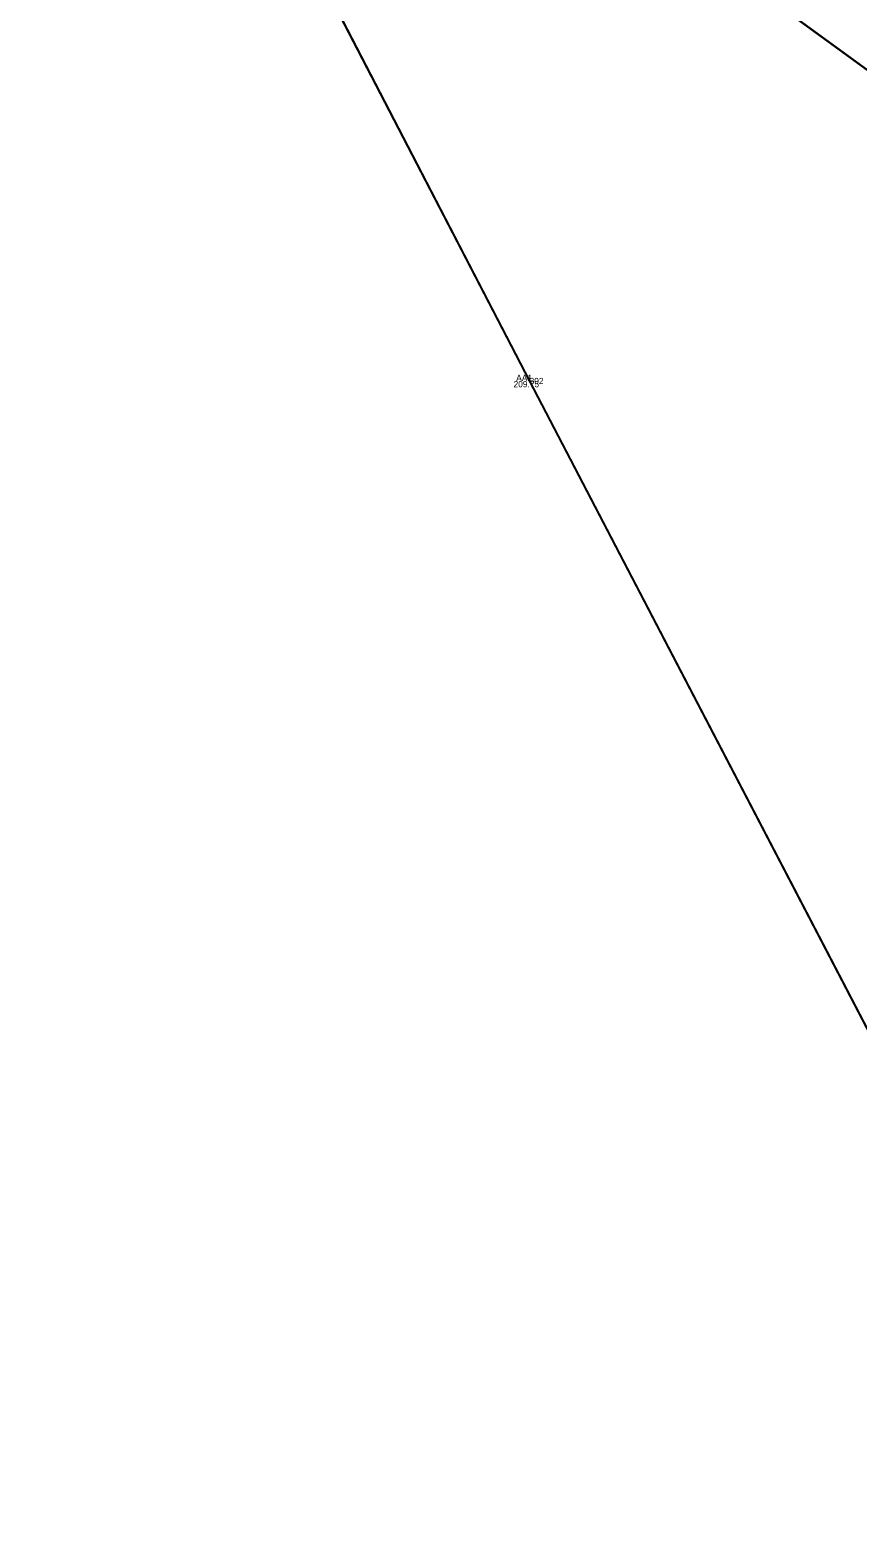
# Model space of a CAD drawing. Extents: x -263091 to -262565, y -1238731 to -1237092.
# Drawn here: x -262982.43 to -262955.92, y -1238442.76 to -1238394.45 of the extents above; entities that cross this region are included whole.
import ezdxf

# ---------------------------------------------------------------- set-up
doc = ezdxf.new("R2010")
doc.units = 0
for name, color, linetype in [('03_Asfalt', 7, 'Continuous'), ('10', 7, 'Continuous'), ('Groma (21)', 7, 'Continuous'), ('Groma (22)', 7, 'Continuous'), ('Groma (23)', 7, 'Continuous'), ('Groma (24)', 7, 'Continuous'), ('U001_Zeleň_mimo', 7, 'Continuous'), ('U002_Asfalt', 7, 'Continuous')]:
    doc.layers.add(name, color=color, linetype=linetype)

msp = doc.modelspace()

# ---------------------------------------------------------------- linework, layer by layer
at = {"layer": '03_Asfalt'}
for points in [[(-262974.83, -1238389.493), (-262966.434, -1238405.689), (-262952.335, -1238432.734), (-262942.188, -1238451.946), (-262934.983, -1238466.187), (-262921.957, -1238491.107), (-262911.861, -1238511.116), (-262905.822, -1238523.977), (-262900.647, -1238535.669), (-262888.764, -1238565.07), (-262881.2, -1238585.494), (-262874.644, -1238603.324)], [(-262804.465, -1238690.033), (-262818.631, -1238655.736), (-262826.695, -1238636.389), (-262836.855, -1238611.872), (-262842.406, -1238598.306), (-262850.452, -1238578.707), (-262858.82, -1238561.234), (-262870.509, -1238539), (-262873.344, -1238533.53), (-262876.375, -1238529.239), (-262880.031, -1238521.826), (-262869.115, -1238517.45), (-262870.175, -1238508.052), (-262871.319, -1238501.744), (-262886.895, -1238462.375), (-262895.067, -1238441.663), (-262905.824, -1238433.621), (-262917.716, -1238423.993), (-262928.896, -1238415.327), (-262941.774, -1238405.784), (-262954.673, -1238396.412), (-262962.054, -1238391.026)]]:
    msp.add_lwpolyline(points, dxfattribs=at)
at = {"layer": '10'}
msp.add_lwpolyline([(-262982.434, -1238375.977), (-262968.907, -1238386.238), (-262962.054, -1238391.026), (-262954.673, -1238396.412), (-262941.774, -1238405.784), (-262928.896, -1238415.327), (-262917.716, -1238423.993), (-262905.824, -1238433.621), (-262895.067, -1238441.663), (-262870.407, -1238460.6)], dxfattribs=at)
at = {"layer": 'Groma (21)'}
msp.add_circle((-262966.434, -1238405.689), 0.01, dxfattribs=at)
at = {"layer": 'U001_Zeleň_mimo'}
for points in [[(-262874.64, -1238603.32), (-262881.2, -1238585.49), (-262888.76, -1238565.07), (-262900.65, -1238535.67), (-262905.82, -1238523.98), (-262911.86, -1238511.12), (-262921.96, -1238491.11), (-262934.98, -1238466.19), (-262942.19, -1238451.95), (-262952.34, -1238432.73), (-262966.43, -1238405.69), (-262974.83, -1238389.49)], [(-262962.05, -1238391.03), (-262954.67, -1238396.41), (-262941.77, -1238405.78), (-262928.9, -1238415.33), (-262917.72, -1238423.99), (-262905.82, -1238433.62), (-262895.07, -1238441.66), (-262886.9, -1238462.38), (-262871.32, -1238501.74), (-262870.18, -1238508.05), (-262869.12, -1238517.45), (-262880.03, -1238521.83), (-262876.38, -1238529.24), (-262873.34, -1238533.53), (-262870.51, -1238539), (-262858.82, -1238561.23), (-262850.45, -1238578.71), (-262842.41, -1238598.31), (-262836.86, -1238611.87), (-262826.7, -1238636.39), (-262818.63, -1238655.74), (-262804.47, -1238690.03)]]:
    msp.add_lwpolyline(points, dxfattribs=at)
at = {"layer": 'U002_Asfalt'}
for points in [[(-262927.57, -1238384.6), (-262931.78, -1238394.73), (-262934.12, -1238396.67), (-262936.84, -1238398.28), (-262939.96, -1238399.18), (-262942.64, -1238399.58), (-262945.06, -1238399.5), (-262944.94, -1238400.58), (-262944.24, -1238401.54), (-262940.47, -1238404.3), (-262927.61, -1238413.71), (-262916.36, -1238422.36), (-262904.85, -1238431.52), (-262898.71, -1238436.38), (-262897.55, -1238437.02), (-262896.94, -1238436.87), (-262895.07, -1238441.66), (-262905.82, -1238433.62), (-262917.72, -1238423.99), (-262928.9, -1238415.33), (-262941.77, -1238405.78), (-262954.67, -1238396.41), (-262962.05, -1238391.03)], [(-262895.07, -1238441.66), (-262905.82, -1238433.62), (-262917.72, -1238423.99), (-262928.9, -1238415.33), (-262941.77, -1238405.78), (-262954.67, -1238396.41), (-262962.05, -1238391.03)]]:
    msp.add_lwpolyline(points, dxfattribs=at)

# ---------------------------------------------------------------- texts
at = {"layer": 'Groma (22)'}
msp.add_text('302', height=0.2, dxfattribs=at).set_placement((-262966.434, -1238405.789))
at = {"layer": 'Groma (23)'}
msp.add_text('209.75', height=0.2, dxfattribs=at).set_placement((-262966.947, -1238405.889))
at = {"layer": 'Groma (24)'}
msp.add_text('AA1', height=0.2, dxfattribs=at).set_placement((-262966.862, -1238405.689))

doc.saveas('drawing.dxf')
